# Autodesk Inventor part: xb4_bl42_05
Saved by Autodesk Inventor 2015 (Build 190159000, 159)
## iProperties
Created: 2018-05
Part Number: xb4_bl42_05
Checked By: TraceParts S.A.
Material: Generic
Catalog Web Link: www.traceparts.com
Document SubType Name: Modeling
Designer: TraceParts
Density: 1 g/cm^3
Appearance: Default
Company: TraceParts S.A.
Author: TraceParts
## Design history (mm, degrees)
feature "xb4_bl42_05.ipt"
body "Solid1"
